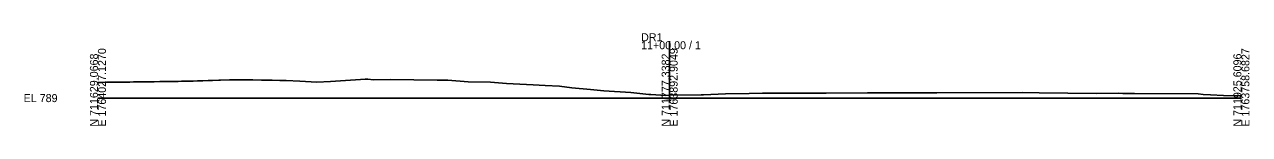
# Model space of a CAD drawing. Extents: x -26 to 403, y -10 to 2023.
# Drawn here: x -25.7 to 402.8, y 1990.3 to 2022.7 of the extents above; entities that cross this region are included whole.
import ezdxf

# ---------------------------------------------------------------- set-up
doc = ezdxf.new("R2010")
doc.units = 0
for name, color, linetype in [('Exist Cross Section Cell', 7, 'Continuous'), ('Exist XS Center Line Elevation Label', 7, 'Continuous'), ('Exist XS Ground Line', 7, 'Continuous')]:
    doc.layers.add(name, color=color, linetype=linetype)

msp = doc.modelspace()

# ---------------------------------------------------------------- linework, layer by layer
at = {"layer": 'Exist Cross Section Cell'}
for p, q in [((200, 2000), (200, 2019.92)), ((0, 2000), (200, 2000)), ((200, 2000), (400, 2000))]:
    msp.add_line(p, q, dxfattribs=at)
at = {"layer": 'Exist XS Ground Line'}
msp.add_lwpolyline([(0, 2005.51), (1.31, 2005.52), (2.94, 2005.54), (5.03, 2005.56), (6.32, 2005.58), (8.76, 2005.6), (9.69, 2005.61), (11.1, 2005.62), (12.48, 2005.64), (13.06, 2005.65), (14.92, 2005.66), (16.43, 2005.68), (17.9, 2005.71), (19.65, 2005.7), (21.7, 2005.79), (25.45, 2005.84), (28.09, 2005.85), (29.25, 2005.88), (29.85, 2005.88), (31.11, 2005.91), (33.29, 2005.98), (34.83, 2006.02), (36.67, 2006.09), (38.56, 2006.17), (40.04, 2006.22), (42.28, 2006.29), (42.89, 2006.31), (45.99, 2006.43), (47.13, 2006.44), (48.5, 2006.43), (49.73, 2006.42), (50.16, 2006.41), (53.53, 2006.37), (54.18, 2006.36), (57.18, 2006.3), (58.81, 2006.28), (60.27, 2006.26), (60.91, 2006.25), (63.64, 2006.22), (64.63, 2006.21), (64.96, 2006.2), (65.88, 2006.16), (70.57, 2005.94), (76.61, 2005.59), (81.35, 2005.76), (91.85, 2006.56), (93.5, 2006.59), (94.4, 2006.64), (96.39, 2006.45), (102.39, 2006.48), (118.72, 2006.29), (122.41, 2006.23), (129.48, 2005.75), (137.31, 2005.53), (142.97, 2005.16), (152.22, 2004.59), (156.46, 2004.39), (161.52, 2004.16), (165.76, 2003.57), (172.34, 2003.06), (176.96, 2002.54), (186.4, 2001.94), (192.74, 2001.3), (193.38, 2001.26), (198.66, 2000.95), (200, 2000.97), (211.01, 2001.15), (211.83, 2001.17), (219.55, 2001.5), (227.77, 2001.64), (232.51, 2001.72), (250.55, 2001.72), (252.98, 2001.72), (254.8, 2001.72), (269.2, 2001.81), (279.14, 2001.87), (284.32, 2001.9), (287.22, 2001.9), (293.47, 2001.9), (323.54, 2001.91), (329.26, 2001.85), (349.28, 2001.63), (356.98, 2001.75), (358.5, 2001.6), (359.91, 2001.57), (362.61, 2001.56), (384.94, 2001.44), (386.59, 2001.26), (389.23, 2001.1), (393.77, 2000.89), (400, 2000.79)], dxfattribs=at)

# ---------------------------------------------------------------- texts
at = {"layer": 'Exist Cross Section Cell'}
for s, p in [('DR1', (190, 2019.92)), ('11+00.00 / 1', (190, 2017.12)), ('EL 789', (-26, 1998.6))]:
    msp.add_text(s, height=2.8, dxfattribs=at).set_placement(p)
for s, p in [('N 711629.0668', (0, 1990)), ('E 1764027.1270', (2.8, 1990)), ('N 711777.3382', (200, 1990)), ('E 1763892.9049', (202.8, 1990)), ('N 711925.6096', (400, 1990)), ('E 1763758.6827', (402.8, 1990))]:
    msp.add_text(s, height=2.8, rotation=90, dxfattribs=at).set_placement(p)
at = {"layer": 'Exist XS Center Line Elevation Label'}
msp.add_text('789.97', height=1, dxfattribs=at).set_placement((197.95, 1998.97))

doc.saveas('drawing.dxf')
